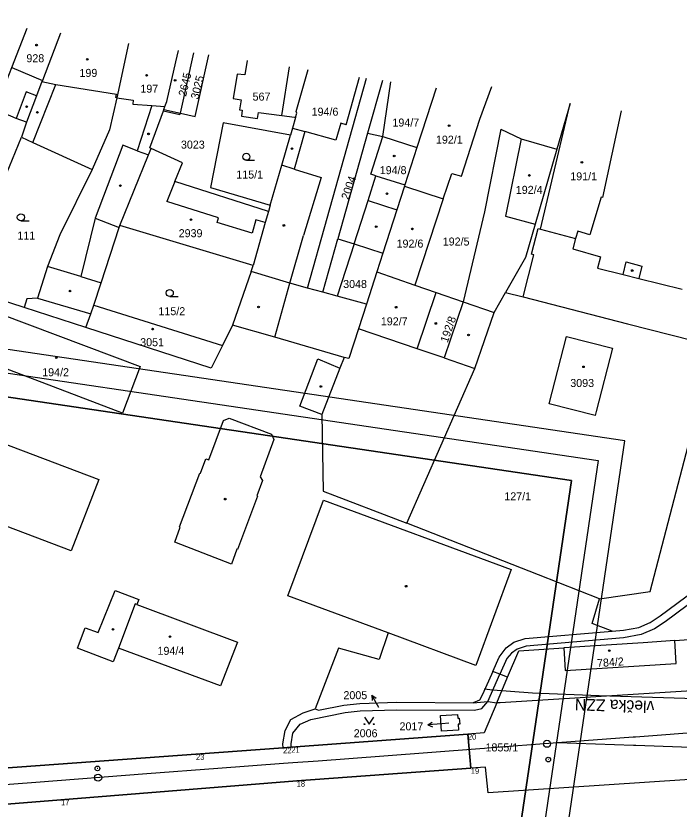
# Model space of a CAD drawing. Extents: x -779330 to -774454, y -1144748 to -1142831.
# Drawn here: x -774928.8 to -774787.8, y -1144444.3 to -1144275.8 of the extents above; entities that cross this region are included whole.
import ezdxf

# ---------------------------------------------------------------- set-up
doc = ezdxf.new("R2010")
doc.units = 0
for name, color, linetype in [('Hranice parcel', 7, 'Continuous'), ('Parcelní čísla', 7, 'Continuous'), ('Pop  PČ popisy', 7, 'Continuous'), ('SŽDC', 7, 'Continuous'), ('Vnitřní kresba', 7, 'Continuous'), ('Vrstva 1', 7, 'Continuous'), ('Vrstva 53', 7, 'Continuous'), ('Vrstva 60', 7, 'Continuous'), ('Vrstva 7', 7, 'Continuous'), ('Značky budov', 7, 'Continuous'), ('Značky kultur', 7, 'Continuous')]:
    doc.layers.add(name, color=color, linetype=linetype)

msp = doc.modelspace()

# ---------------------------------------------------------------- linework, layer by layer
at = {"layer": 'Hranice parcel'}
for p, q in [((-774893.78, -1144296.41), (-774890.92, -1144283.59)), ((-774866.73, -1144333.6), (-774854.2, -1144289.03)), ((-774850.85, -1144289.52), (-774853.99, -1144300.71)), ((-774839.44, -1144291.11), (-774843.52, -1144303.75)), ((-774810.96, -1144294.39), (-774813.77, -1144304.08)), ((-774926.52, -1144298.36), (-774927.54, -1144301.56)), ((-774853.99, -1144300.71), (-774860.29, -1144323.14)), ((-774940.69, -1144333.27), (-774927.54, -1144301.56)), ((-774846.16, -1144311.97), (-774837.89, -1144314.64)), ((-774837.89, -1144314.64), (-774843.96, -1144332.95)), ((-774874.7, -1144315.99), (-774875.08, -1144317.3)), ((-774878.28, -1144328.8), (-774906.64, -1144320.27)), ((-774863.47, -1144334.48), (-774860.29, -1144323.14)), ((-774850.74, -1144326.17), (-774852.02, -1144330.16)), ((-774878.71, -1144330.05), (-774878.28, -1144328.8)), ((-774852.02, -1144330.16), (-774854.24, -1144337.04)), ((-774852.02, -1144330.16), (-774843.96, -1144332.95)), ((-774843.96, -1144332.95), (-774839.41, -1144334.53)), ((-774927, -1144337.72), (-774940.69, -1144333.27)), ((-774863.47, -1144334.48), (-774866.73, -1144333.6)), ((-774843.47, -1144346.47), (-774839.41, -1144334.53)), ((-774839.41, -1144334.53), (-774833.68, -1144336.52)), ((-774913.86, -1144341.97), (-774927, -1144337.72)), ((-774912.2, -1144337.19), (-774884.85, -1144345.82)), ((-774854.24, -1144337.04), (-774855.92, -1144342.24)), ((-774843.47, -1144346.47), (-774855.92, -1144342.24)), ((-774788.71, -1144408.47), (-774749.65, -1144405.72)), ((-774824.22, -1144416.24), (-774825.86, -1144415.63)), ((-774826.54, -1144421.73), (-774824.22, -1144416.24)), ((-774828.44, -1144421.43), (-774826.54, -1144421.73)), ((-774832.66, -1144428.33), (-774870.21, -1144431.11)), ((-774832.66, -1144428.33), (-774832.04, -1144435.58)), ((-774870.21, -1144431.11), (-774871.96, -1144431.24))]:
    msp.add_line(p, q, dxfattribs=at)
for points in [[(-774926.52, -1144298.36), (-774928.67, -1144297.54), (-774933.15, -1144295.62), (-774929.64, -1144286.74), (-774926.35, -1144278.39)], [(-774919.28, -1144279.44), (-774923.12, -1144289.46), (-774923.21, -1144289.71), (-774924.38, -1144292.76), (-774926.52, -1144298.36)], [(-774904.78, -1144281.6), (-774907.28, -1144293.19), (-774908.84, -1144299.98), (-774912.54, -1144308.38)], [(-774897.4, -1144295.94), (-774897.28, -1144295.62), (-774897.07, -1144295.04), (-774896.68, -1144293.96), (-774894.72, -1144285.56), (-774894.18, -1144283.12)], [(-774893.78, -1144296.41), (-774890.67, -1144297.11), (-774887.75, -1144284.05)], [(-774879.56, -1144285.28), (-774880.06, -1144288.28), (-774881.72, -1144288.14), (-774882.56, -1144293.33), (-774880.89, -1144293.6), (-774881.2, -1144295.73), (-774880.63, -1144295.81), (-774880.81, -1144297.08), (-774877.38, -1144297.6), (-774877.2, -1144296.27), (-774872.18, -1144296.96), (-774869.53, -1144297.29), (-774869.28, -1144297.32)], [(-774869.28, -1144297.32), (-774869.02, -1144296.42), (-774869.19, -1144296.07), (-774866.6, -1144287.19)], [(-774837.89, -1144314.64), (-774836.11, -1144309.23), (-774834.01, -1144309.82), (-774830.14, -1144297.71), (-774827.58, -1144290.74)], [(-774900.01, -1144303.91), (-774900.24, -1144303.82), (-774897.4, -1144295.94)], [(-774897.4, -1144295.94), (-774893.86, -1144296.73), (-774893.78, -1144296.41)], [(-774869.28, -1144297.32), (-774869.95, -1144299.63), (-774870.37, -1144301.08)], [(-774870.37, -1144301.08), (-774884.68, -1144298.48), (-774887.41, -1144312.22), (-774874.7, -1144315.99)], [(-774874.7, -1144315.99), (-774872.23, -1144307.48), (-774870.37, -1144301.08)], [(-774853.99, -1144300.71), (-774850.78, -1144301.42), (-774843.52, -1144303.75)], [(-774825.63, -1144299.86), (-774829.16, -1144317.4), (-774833.68, -1144336.52)], [(-774825.63, -1144299.86), (-774821.36, -1144301.89), (-774813.77, -1144304.08)], [(-774927.54, -1144301.56), (-774925.13, -1144302.69), (-774912.54, -1144308.38)], [(-774906.64, -1144320.27), (-774900.57, -1144305.31), (-774900.01, -1144303.91)], [(-774875.08, -1144317.3), (-774894.95, -1144310.97), (-774893.3, -1144306.99), (-774900.01, -1144303.91)], [(-774843.52, -1144303.75), (-774846.07, -1144311.68), (-774846.16, -1144311.97)], [(-774813.77, -1144304.08), (-774818.37, -1144320.02), (-774820.43, -1144327.09), (-774824.66, -1144334.51)], [(-774912.54, -1144308.38), (-774919.42, -1144322.31), (-774922.03, -1144328.99), (-774924.14, -1144335.71), (-774926.42, -1144335.89), (-774927, -1144337.72)], [(-774846.16, -1144311.97), (-774847.76, -1144316.94), (-774850.74, -1144326.17)], [(-774875.08, -1144317.3), (-774875.75, -1144319.63), (-774878.28, -1144328.8)], [(-774912.2, -1144337.19), (-774910.64, -1144332.46), (-774906.8, -1144320.74), (-774906.64, -1144320.27)], [(-774860.29, -1144323.14), (-774856.87, -1144324.2), (-774850.74, -1144326.17)], [(-774878.71, -1144330.05), (-774882.69, -1144341.48), (-774884.85, -1144345.82)], [(-774866.73, -1144333.6), (-774870.5, -1144332.58), (-774878.71, -1144330.05)], [(-774854.24, -1144337.04), (-774860.45, -1144335.29), (-774863.47, -1144334.48)], [(-774845.62, -1144383.56), (-774831.16, -1144350.65), (-774827.09, -1144338.8), (-774824.66, -1144334.51)], [(-774824.66, -1144334.51), (-774820.92, -1144335.47), (-774798.77, -1144341.16), (-774780.31, -1144345.89)], [(-774833.68, -1144336.52), (-774837.74, -1144348.41), (-774843.47, -1144346.47)], [(-774913.86, -1144341.97), (-774912.82, -1144339.08), (-774912.2, -1144337.19)], [(-774902.35, -1144350.28), (-774906.07, -1144360.14), (-774935.48, -1144349), (-774931.84, -1144339.13), (-774902.35, -1144350.28)], [(-774884.85, -1144345.82), (-774887.22, -1144350.6), (-774913.86, -1144341.97)], [(-774855.92, -1144342.24), (-774857.95, -1144348.55), (-774858.99, -1144348.34), (-774859.86, -1144350.58), (-774863.72, -1144360.44), (-774863.41, -1144376.75), (-774845.62, -1144383.56)], [(-774805.38, -1144359.83), (-774805.62, -1144360.66), (-774815.36, -1144358.16), (-774811.7, -1144343.89), (-774801.96, -1144346.39), (-774805.38, -1144359.83)], [(-774801.98, -1144406.47), (-774799.57, -1144406.26), (-774796.3, -1144405.69), (-774793.89, -1144404.6), (-774791.79, -1144403.24), (-774759.55, -1144379.36), (-774721.28, -1144350.96)], [(-774804.69, -1144399.57), (-774793.9, -1144398.06), (-774782, -1144352.41)], [(-774722.22, -1144353.64), (-774758.58, -1144380.6), (-774790.75, -1144404.47), (-774793.02, -1144405.95), (-774795.8, -1144407.18), (-774799.56, -1144407.9), (-774820.31, -1144409.63), (-774822.18, -1144410.3), (-774823.4, -1144411.16), (-774824.38, -1144412.31), (-774825.86, -1144415.63)], [(-774952.35, -1144376.06), (-774948.54, -1144366.12), (-774946.53, -1144360.9), (-774911.14, -1144374.27), (-774916.98, -1144389.4), (-774952.35, -1144376.06)], [(-774804.69, -1144399.57), (-774817.65, -1144394.5), (-774845.62, -1144383.56)], [(-774885.25, -1144418.1), (-774906.94, -1144410.06), (-774908.07, -1144413.02), (-774915.67, -1144410.12), (-774914.01, -1144405.75), (-774911.26, -1144406.79), (-774907.66, -1144397.86), (-774902.6, -1144399.78), (-774903, -1144400.82), (-774881.66, -1144408.82), (-774885.25, -1144418.1)], [(-774801.98, -1144406.47), (-774806.23, -1144404.86), (-774804.69, -1144399.57)], [(-774825.86, -1144415.63), (-774827.39, -1144415.07), (-774826.04, -1144411.98), (-774824.53, -1144410), (-774822.89, -1144408.84), (-774820.5, -1144408.04), (-774801.98, -1144406.47)], [(-774749.65, -1144405.72), (-774750.72, -1144408.24), (-774751.62, -1144410.36), (-774752.94, -1144413.48), (-774754.55, -1144417.27), (-774825.82, -1144421.69), (-774826.54, -1144421.73)], [(-774454, -1144408.27), (-774492.93, -1144411.59), (-774550.57, -1144426.11), (-774550.13, -1144433.51), (-774643.48, -1144453.01), (-774648.56, -1144453.29), (-774652.59, -1144453.21), (-774659.68, -1144452.39), (-774671.53, -1144449.5), (-774677.59, -1144447.3), (-774684.17, -1144444.45), (-774696.63, -1144438.42), (-774701.94, -1144435.76), (-774705.42, -1144434.73), (-774709.64, -1144434.17), (-774760.86, -1144436.38), (-774828.33, -1144440.79), (-774828.91, -1144435.35), (-774832.04, -1144435.58)], [(-774788.71, -1144408.47), (-774795.44, -1144408.94), (-774812.25, -1144410.04)], [(-774812.25, -1144410.04), (-774811.97, -1144414.8), (-774788.39, -1144413.36), (-774788.71, -1144408.47)], [(-774824.22, -1144416.24), (-774821.85, -1144410.67), (-774812.25, -1144410.04)], [(-774871.96, -1144431.24), (-774872.02, -1144430.41), (-774871.48, -1144427.55), (-774870.28, -1144425.27), (-774867.69, -1144423.82), (-774865.1, -1144422.99), (-774864.41, -1144423.23), (-774859, -1144422.2), (-774855.6, -1144421.82), (-774847.74, -1144421.57), (-774831.56, -1144421.69), (-774828.44, -1144421.43)], [(-774870.21, -1144431.11), (-774870.26, -1144430.4), (-774869.86, -1144428.16), (-774868.34, -1144426.23), (-774866.07, -1144425.23), (-774858.72, -1144423.78), (-774855.55, -1144423.4), (-774847.74, -1144423.16), (-774831.25, -1144423.26), (-774829.7, -1144422.88), (-774828.44, -1144421.43)], [(-774826.54, -1144421.73), (-774829.24, -1144428.08), (-774832.66, -1144428.33)], [(-774834.87, -1144424.15), (-774834.81, -1144424.99), (-774834.5, -1144424.97), (-774834.41, -1144426.21), (-774834.72, -1144426.24), (-774834.63, -1144427.47), (-774838.26, -1144427.74), (-774838.49, -1144424.4), (-774834.87, -1144424.15)], [(-775003.31, -1144440.57), (-774957.77, -1144437.47), (-774890.46, -1144432.61), (-774871.96, -1144431.24)], [(-774832.04, -1144435.58), (-774869.06, -1144438.3), (-774919.16, -1144442.27), (-774942.23, -1144444.12), (-775006.07, -1144448.84), (-775047.73, -1144454.47), (-775049.08, -1144458.29), (-775076.86, -1144459.23)]]:
    msp.add_lwpolyline(points, dxfattribs=at)
at = {"layer": 'Pop  PČ popisy'}
for p, q in [((-774851.6, -1144422.66), (-774853.1, -1144420.06)), ((-774853.1, -1144420.06), (-774852.17, -1144420.68)), ((-774853.1, -1144420.06), (-774853.03, -1144421.18)), ((-774851.6, -1144422.67), (-774851.6, -1144422.66)), ((-774841.19, -1144426.35), (-774840.23, -1144425.78)), ((-774838.2, -1144426.14), (-774841.19, -1144426.35)), ((-774841.19, -1144426.35), (-774840.16, -1144426.78)), ((-774836.71, -1144426.02), (-774838.2, -1144426.14))]:
    msp.add_line(p, q, dxfattribs=at)
at = {"layer": 'SŽDC'}
msp.add_lwpolyline([(-774942.23, -1144444.12), (-774919.16, -1144442.27), (-774869.06, -1144438.3), (-774832.04, -1144435.58), (-774832.66, -1144428.33), (-774870.21, -1144431.11), (-774871.96, -1144431.24), (-774890.46, -1144432.61), (-774957.77, -1144437.47)], dxfattribs=at)
at = {"layer": 'Vnitřní kresba'}
for p, q in [((-774929.64, -1144286.74), (-774923.12, -1144289.46)), ((-774872.18, -1144296.96), (-774870.57, -1144286.6)), ((-774858.55, -1144298.94), (-774855.71, -1144288.79)), ((-774925.13, -1144302.69), (-774920.27, -1144290.35)), ((-774923.21, -1144289.71), (-774920.27, -1144290.35)), ((-774920.27, -1144290.35), (-774907.36, -1144292.41)), ((-774850.78, -1144301.42), (-774849.03, -1144289.78)), ((-774926.53, -1144291.93), (-774928.67, -1144297.54)), ((-774924.38, -1144292.76), (-774926.53, -1144291.93)), ((-774907.5, -1144293.14), (-774907.36, -1144292.41)), ((-774907.28, -1144293.19), (-774907.5, -1144293.14)), ((-774907.28, -1144293.19), (-774903.81, -1144293.67)), ((-774903.81, -1144293.67), (-774903.87, -1144294.52)), ((-774817.22, -1144321.04), (-774810.96, -1144294.39)), ((-774903.87, -1144294.52), (-774899.85, -1144294.83)), ((-774899.85, -1144294.83), (-774902.94, -1144304.4)), ((-774899.85, -1144294.83), (-774897.07, -1144295.04)), ((-774897.28, -1144295.62), (-774893.78, -1144296.41)), ((-774800.08, -1144295.92), (-774804.08, -1144314.36)), ((-774859.68, -1144298.59), (-774860.74, -1144302.2)), ((-774858.55, -1144298.94), (-774859.68, -1144298.59)), ((-774869.95, -1144299.63), (-774867.32, -1144300.36)), ((-774867.32, -1144300.36), (-774869.56, -1144308.32)), ((-774860.74, -1144302.2), (-774867.32, -1144300.36)), ((-774853.3, -1144309.42), (-774850.78, -1144301.42)), ((-774821.36, -1144301.89), (-774824.66, -1144318.3)), ((-774906.01, -1144303.22), (-774911.9, -1144318.72)), ((-774902.94, -1144304.4), (-774906.01, -1144303.22)), ((-774902.94, -1144304.4), (-774900.57, -1144305.31)), ((-774869.56, -1144308.32), (-774872.23, -1144307.48)), ((-774869.56, -1144308.32), (-774863.86, -1144310.11)), ((-774852.2, -1144309.76), (-774853.3, -1144309.42)), ((-774894.95, -1144310.97), (-774896.69, -1144315.17)), ((-774863.86, -1144310.11), (-774867.63, -1144322.44)), ((-774853.88, -1144314.97), (-774852.2, -1144309.76)), ((-774852.2, -1144309.76), (-774846.07, -1144311.68)), ((-774804.37, -1144314.28), (-774806.72, -1144322.27)), ((-774804.08, -1144314.36), (-774804.37, -1144314.28)), ((-774885.65, -1144318.69), (-774896.69, -1144315.17)), ((-774856.87, -1144324.2), (-774853.88, -1144314.97)), ((-774853.88, -1144314.97), (-774847.76, -1144316.94)), ((-774911.9, -1144318.72), (-774914.95, -1144331.15)), ((-774911.9, -1144318.72), (-774906.8, -1144320.74)), ((-774885.95, -1144319.64), (-774885.65, -1144318.69)), ((-774878.55, -1144321.92), (-774885.95, -1144319.64)), ((-774877.72, -1144319.06), (-774878.55, -1144321.92)), ((-774875.75, -1144319.63), (-774877.72, -1144319.06)), ((-774824.66, -1144318.3), (-774818.37, -1144320.02)), ((-774819.12, -1144326.38), (-774817.7, -1144320.92)), ((-774817.7, -1144320.92), (-774817.22, -1144321.04)), ((-774817.22, -1144321.04), (-774809.77, -1144323.09)), ((-774870.5, -1144332.58), (-774867.63, -1144322.44)), ((-774809.77, -1144323.09), (-774810.37, -1144325.28)), ((-774809.33, -1144321.5), (-774809.77, -1144323.09)), ((-774806.72, -1144322.27), (-774809.33, -1144321.5)), ((-774856.87, -1144324.2), (-774860.45, -1144335.29)), ((-774818.63, -1144326.51), (-774819.12, -1144326.38)), ((-774810.37, -1144325.28), (-774804.47, -1144326.92)), ((-774820.92, -1144335.47), (-774818.63, -1144326.51)), ((-774804.47, -1144326.92), (-774805.13, -1144329.38)), ((-774799.66, -1144330.73), (-774799, -1144328.05)), ((-774799, -1144328.05), (-774795.66, -1144328.94)), ((-774914.95, -1144331.15), (-774922.03, -1144328.99)), ((-774805.13, -1144329.38), (-774799.66, -1144330.73)), ((-774795.66, -1144328.94), (-774796.31, -1144331.56)), ((-774914.95, -1144331.15), (-774910.64, -1144332.46)), ((-774799.66, -1144330.73), (-774796.31, -1144331.56)), ((-774873.73, -1144344.05), (-774870.5, -1144332.58)), ((-774796.31, -1144331.56), (-774787.13, -1144333.84)), ((-774924.14, -1144335.71), (-774912.82, -1144339.08)), ((-774833.68, -1144336.52), (-774827.09, -1144338.8)), ((-774873.73, -1144344.05), (-774882.69, -1144341.48)), ((-774858.99, -1144348.34), (-774873.73, -1144344.05)), ((-774868.38, -1144358.66), (-774864.54, -1144348.65)), ((-774864.54, -1144348.65), (-774859.86, -1144350.58)), ((-774837.74, -1144348.41), (-774831.16, -1144350.65)), ((-774863.72, -1144360.44), (-774868.38, -1144358.66)), ((-774887.73, -1144370.07), (-774884.58, -1144361.71)), ((-774884.58, -1144361.71), (-774883.44, -1144361.25)), ((-774883.44, -1144361.25), (-774874.4, -1144364.63)), ((-774874.4, -1144364.63), (-774873.91, -1144365.74)), ((-774873.91, -1144365.74), (-774876.81, -1144373.7)), ((-774889.53, -1144372.93), (-774888.38, -1144369.85)), ((-774888.38, -1144369.85), (-774887.73, -1144370.07)), ((-774893.94, -1144384.31), (-774889.67, -1144372.88)), ((-774889.67, -1144372.88), (-774889.53, -1144372.93)), ((-774876.33, -1144374.46), (-774877.55, -1144377.73)), ((-774876.81, -1144373.7), (-774876.33, -1144374.46)), ((-774877.41, -1144377.78), (-774881.61, -1144389.11)), ((-774877.55, -1144377.73), (-774877.41, -1144377.78)), ((-774870.95, -1144398.98), (-774863.38, -1144378.61)), ((-774863.38, -1144378.61), (-774823.46, -1144393.35)), ((-774894.99, -1144387.55), (-774893.8, -1144384.37)), ((-774893.8, -1144384.37), (-774893.94, -1144384.31)), ((-774882.93, -1144392.23), (-774894.99, -1144387.55)), ((-774881.75, -1144389.05), (-774882.93, -1144392.23)), ((-774881.61, -1144389.11), (-774881.75, -1144389.05)), ((-774823.46, -1144393.35), (-774830.99, -1144413.74)), ((-774849.61, -1144406.86), (-774870.95, -1144398.98)), ((-774903.37, -1144400.67), (-774906.94, -1144410.06)), ((-774903, -1144400.82), (-774903.37, -1144400.67)), ((-774849.61, -1144406.86), (-774851.49, -1144412.52)), ((-774830.99, -1144413.74), (-774849.61, -1144406.86)), ((-774860.16, -1144410.07), (-774865.1, -1144422.99)), ((-774851.49, -1144412.52), (-774860.16, -1144410.07)), ((-774827.39, -1144415.07), (-774829.53, -1144419.94)), ((-774828.44, -1144421.43), (-774825.86, -1144415.63)), ((-774829.53, -1144419.94), (-774830.18, -1144421.12)), ((-774830.18, -1144421.12), (-774831.56, -1144421.69))]:
    msp.add_line(p, q, dxfattribs=at)
at = {"layer": 'Vrstva 1'}
for points in [[(-774799.29, -1144366.04), (-776045.7, -1144181.56), (-776089.18, -1144475.34), (-774842.77, -1144659.83)], [(-774846.98, -1144654.15), (-776083.5, -1144471.13), (-776041.48, -1144187.23), (-774804.97, -1144370.25)], [(-774810.64, -1144374.46), (-775834.48, -1144222.92), (-775875.04, -1144496.94), (-774851.19, -1144648.48)], [(-774851.19, -1144648.48), (-775875.04, -1144496.94), (-775834.48, -1144222.92), (-774810.64, -1144374.46)]]:
    msp.add_lwpolyline(points, close=True, dxfattribs=at)
for points in [[(-774779.78, -1144421), (-774804.73, -1144420.22), (-774818.9, -1144419.64), (-774827.35, -1144419), (-774829.24, -1144418.79)], [(-774694.69, -1144426.13), (-774721.06, -1144428.11), (-774736.69, -1144429.29), (-774763.81, -1144431.14), (-774775.1, -1144431.37), (-774787.23, -1144431.13), (-774796.99, -1144430.79), (-774797.44, -1144430.78), (-774813.59, -1144430.23), (-774828.58, -1144431.36), (-774829.12, -1144431.4), (-774830.16, -1144431.48)], [(-774764.4, -1144426.51), (-774781.47, -1144427.81), (-774797.03, -1144428.98), (-774797.52, -1144429.01), (-774813.59, -1144430.23), (-774828.58, -1144431.36), (-774829.12, -1144431.4), (-774830.16, -1144431.48)], [(-774830.16, -1144431.48), (-774850.56, -1144433.02), (-774864.47, -1144434.06), (-774869.91, -1144434.47), (-774871.83, -1144434.62), (-774885.85, -1144435.68), (-774900.88, -1144436.8), (-774924.49, -1144438.59), (-774948.04, -1144440.36), (-774972.39, -1144442.2), (-774996.53, -1144444.02), (-775020.06, -1144445.79), (-775040.38, -1144447.31), (-775053.94, -1144448.33), (-775072.56, -1144449.73), (-775089.15, -1144450.96), (-775106.82, -1144452.3), (-775129.87, -1144454.04), (-775154.33, -1144455.87), (-775163.87, -1144456.59), (-775186.75, -1144458.31), (-775211.37, -1144460.17), (-775237.52, -1144462.13)]]:
    msp.add_lwpolyline(points, dxfattribs=at)
at = {"layer": 'Vrstva 53'}
msp.add_lwpolyline([(-774957.77, -1144437.47), (-774890.46, -1144432.61), (-774871.96, -1144431.24), (-774870.21, -1144431.11), (-774832.66, -1144428.33), (-774832.04, -1144435.58), (-774869.06, -1144438.3), (-774919.16, -1144442.27), (-774942.23, -1144444.12)], dxfattribs=at)
msp.add_lwpolyline([(-774957.77, -1144437.47), (-774890.46, -1144432.61), (-774871.96, -1144431.24), (-774870.21, -1144431.11), (-774832.66, -1144428.33), (-774832.04, -1144435.58), (-774869.06, -1144438.3), (-774919.16, -1144442.27), (-774942.23, -1144444.12)], dxfattribs=at)
at = {"layer": 'Vrstva 60'}
for p, q in [((-774832.66, -1144428.33), (-774832.66, -1144428.33)), ((-774890.46, -1144432.61), (-774890.46, -1144432.61)), ((-774871.96, -1144431.24), (-774871.96, -1144431.24)), ((-774870.21, -1144431.11), (-774870.21, -1144431.11)), ((-774832.04, -1144435.58), (-774832.04, -1144435.58)), ((-774869.06, -1144438.3), (-774869.06, -1144438.3)), ((-774919.16, -1144442.27), (-774919.16, -1144442.27))]:
    msp.add_line(p, q, dxfattribs=at)
at = {"layer": 'Vrstva 7'}
for p, q in [((-774815.53, -1144433.76), (-774815.63, -1144433.76)), ((-774911.35, -1144435.64), (-774911.45, -1144435.65))]:
    msp.add_line(p, q, dxfattribs=at)
for centre, radius in [((-774815.85, -1144430.4), 0.75), ((-774815.58, -1144433.76), 0.5), ((-774911.4, -1144435.64), 0.5), ((-774911.26, -1144437.59), 0.75)]:
    msp.add_circle(centre, radius, dxfattribs=at)
at = {"layer": 'Značky budov'}
for centre in [(-774924.36, -1144281.97), (-774913.57, -1144284.98), (-774900.96, -1144288.39), (-774894.9, -1144289.46), (-774926.47, -1144295.06), (-774924.17, -1144296.26), (-774836.66, -1144299.09), (-774900.55, -1144300.83), (-774870.05, -1144303.97), (-774848.32, -1144305.52), (-774808.43, -1144306.88), (-774819.59, -1144309.66), (-774906.54, -1144311.82), (-774849.86, -1144313.55), (-774891.52, -1144319.05), (-774871.78, -1144320.28), (-774852.15, -1144320.56), (-774844.46, -1144321.01), (-774797.74, -1144329.87), (-774917.23, -1144334.22), (-774877.17, -1144337.6), (-774847.92, -1144337.65), (-774839.48, -1144341.11), (-774899.68, -1144342.31), (-774832.53, -1144343.54), (-774920.15, -1144348.39), (-774808.09, -1144350.32), (-774863.92, -1144354.5), (-774884.25, -1144378.43), (-774845.8, -1144396.93), (-774908.09, -1144406.1), (-774895.98, -1144407.64), (-774802.61, -1144410.61)]:
    msp.add_circle(centre, 0.175, dxfattribs=at)
at = {"layer": 'Značky kultur'}
for p, q in [((-774879.75, -1144306.45), (-774878, -1144306.45)), ((-774927.69, -1144319.31), (-774925.94, -1144319.31)), ((-774896.03, -1144335.38), (-774894.28, -1144335.38))]:
    msp.add_line(p, q, dxfattribs=at)
msp.add_lwpolyline([(-774854.67, -1144424.73), (-774853.67, -1144426.23), (-774852.67, -1144424.73)], dxfattribs=at)
for centre, radius in [((-774879.75, -1144305.7), 0.75), ((-774927.69, -1144318.56), 0.75), ((-774896.03, -1144334.63), 0.75), ((-774854.67, -1144426.23), 0.1), ((-774852.67, -1144426.23), 0.1)]:
    msp.add_circle(centre, radius, dxfattribs=at)

# ---------------------------------------------------------------- texts
at = {"layer": 'Parcelní čísla'}
for s, p in [('928', (-774926.51, -1144285.61)), ('199', (-774915.23, -1144288.73)), ('197', (-774902.28, -1144292.08)), ('567', (-774878.43, -1144293.77)), ('194/6', (-774865.88, -1144296.97)), ('194/7', (-774848.7, -1144299.27)), ('192/1', (-774839.45, -1144302.91)), ('3023', (-774893.66, -1144303.96)), ('194/8', (-774851.4, -1144309.39)), ('115/1', (-774881.89, -1144310.32)), ('191/1', (-774810.9, -1144310.7)), ('192/4', (-774822.48, -1144313.57)), ('2939', (-774894.14, -1144322.78)), ('111', (-774928.42, -1144323.28)), ('192/5', (-774838.01, -1144324.55)), ('192/6', (-774847.82, -1144324.99)), ('3048', (-774859.18, -1144333.57)), ('115/2', (-774898.44, -1144339.35)), ('192/7', (-774851.17, -1144341.51)), ('3051', (-774902.32, -1144345.94)), ('194/2', (-774923.15, -1144352.31)), ('3093', (-774810.9, -1144354.6)), ('127/1', (-774824.92, -1144378.68)), ('194/4', (-774898.64, -1144411.5)), ('2005', (-774859.12, -1144420.92)), ('2017', (-774847.2, -1144427.54)), ('2006', (-774856.93, -1144429.01)), ('1855/1', (-774828.92, -1144432.02))]:
    msp.add_text(s, height=1.7, dxfattribs=at).set_placement(p)
for s, rotation, p in [('2645', 77, (-774892.57, -1144292.97)), ('3025', 76, (-774889.97, -1144293.6)), ('2004', 71, (-774858.04, -1144314.94)), ('192/8', 71, (-774836.98, -1144345.31)), ('784/2', 4, (-774805.16, -1144414.12))]:
    msp.add_text(s, height=1.7, rotation=rotation, dxfattribs=at).set_placement(p)
at = {"layer": 'Vrstva 1'}
msp.add_text('vlečka ZZN', height=2.5, rotation=178.212, dxfattribs=at).set_placement((-774792.99, -1144421.32))
at = {"layer": 'Vrstva 60'}
for s, p in [('20', (-774832.66, -1144429.53)), ('23', (-774890.46, -1144433.81)), ('22', (-774871.96, -1144432.44)), ('21', (-774870.21, -1144432.31)), ('19', (-774832.04, -1144436.78)), ('18', (-774869.06, -1144439.5)), ('17', (-774919.16, -1144443.47))]:
    msp.add_text(s, height=1.2, dxfattribs=at).set_placement(p)

doc.saveas('drawing.dxf')
